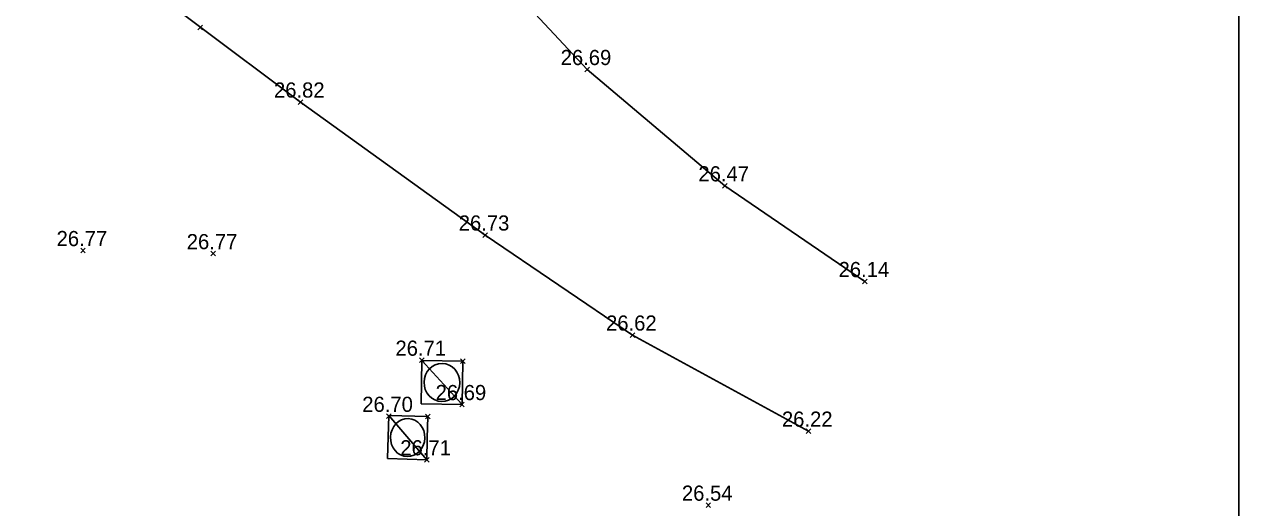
# Model space of a CAD drawing. Extents: x 37864 to 38032, y 453991 to 454052.
# Drawn here: x 37923.19 to 37946.06, y 454028.87 to 454037.97 of the extents above; entities that cross this region are included whole.
import ezdxf

# ---------------------------------------------------------------- set-up
doc = ezdxf.new("R2010")
doc.units = 0
for name, color, linetype in [('DH_CALCUL SURFACE-TEXTE', 7, 'Continuous'), ('GO_POTEAU', 7, 'Continuous'), ('SO_MENUISERIE EXT DOR', 7, 'Continuous'), ('SO_SANITAIRE DETAILLE', 7, 'Continuous')]:
    doc.layers.add(name, color=color, linetype=linetype)

# ---------------------------------------------------------------- blocks, each defined once
blk = doc.blocks.new('A-REGARD')
for p, q in [((0, 1), (1, 1)), ((0, 0), (1, 1)), ((0, 0), (0, 1)), ((1, 1), (1, 0)), ((0.5, 0), (0, 0)), ((1, 0), (0.5, 0))]:
    blk.add_line(p, q)
blk.add_circle((0.5, 0.5), 0.438)
blk = doc.blocks.new('POINT_DISPLAY')
for p, q in [((-0.04375, -0.04375), (0.04375, 0.04375)), ((-0.04375, 0.04375), (0.04375, -0.04375))]:
    blk.add_line(p, q)
blk = doc.blocks.new('POINTCOT')
blk.add_blockref('POINT_DISPLAY', (0, 0))

msp = doc.modelspace()

# ---------------------------------------------------------------- linework, layer by layer
at = {"layer": 'DEFPOINTS'}
msp.add_lwpolyline([(37864.064, 453990.816), (37946.064, 453990.816), (37946.064, 454048.216), (37864.064, 454048.216)], close=True, dxfattribs=at)
at = {"layer": 'SO_SANITAIRE DETAILLE'}
for points in [[(37939.024, 454033.13), (37936.384, 454034.931), (37933.79, 454037.12), (37931.475, 454039.605), (37929.998, 454041.432), (37929.601, 454042.679)], [(37921.361, 454042.24), (37924.438, 454039.473), (37928.39, 454036.508), (37931.87, 454034.006), (37934.645, 454032.123), (37937.958, 454030.315)]]:
    msp.add_lwpolyline(points, dxfattribs=at)

# ---------------------------------------------------------------- block references
at = {"layer": 'DH_CALCUL SURFACE-TEXTE', "rotation": 2.2526485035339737e-05}
for p in [(37926.5, 454037.909), (37933.79, 454037.12), (37928.39, 454036.508), (37936.384, 454034.931), (37931.87, 454034.006), (37924.295, 454033.713), (37926.747, 454033.656), (37939.024, 454033.13), (37934.645, 454032.123), (37930.678, 454031.65), (37931.448, 454031.634), (37931.434, 454030.815), (37930.053, 454030.595), (37930.792, 454030.591), (37937.958, 454030.315), (37930.769, 454029.777), (37936.074, 454028.922)]:
    msp.add_blockref('POINTCOT', p, dxfattribs=at)
at = {"layer": 'SO_MENUISERIE EXT DOR'}
for p, xscale, yscale, rotation in [((37931.434, 454030.815), 0.8187694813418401, 0.7698954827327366, 89.03439860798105), ((37930.769, 454029.777), 0.81454941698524, 0.7392680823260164, 88.37545264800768)]:
    msp.add_blockref('A-REGARD', p, dxfattribs=dict(at, xscale=xscale, yscale=yscale, rotation=rotation))

# ---------------------------------------------------------------- texts
at = {"layer": 'GO_POTEAU'}
for s, p in [('26.69', (37933.292, 454037.204)), ('26.82', (37927.892, 454036.592)), ('26.47', (37935.886, 454035.015)), ('26.73', (37931.372, 454034.09)), ('26.77', (37923.797, 454033.797)), ('26.77', (37926.249, 454033.739)), ('26.14', (37938.526, 454033.214)), ('26.62', (37934.147, 454032.207)), ('26.71', (37930.18, 454031.734)), ('26.69', (37930.936, 454030.899)), ('26.70', (37929.555, 454030.678)), ('26.22', (37937.46, 454030.399)), ('26.71', (37930.271, 454029.86)), ('26.54', (37935.576, 454029.006))]:
    msp.add_text(s, height=0.285, rotation=0, dxfattribs=at).set_placement(p)

doc.saveas('drawing.dxf')
